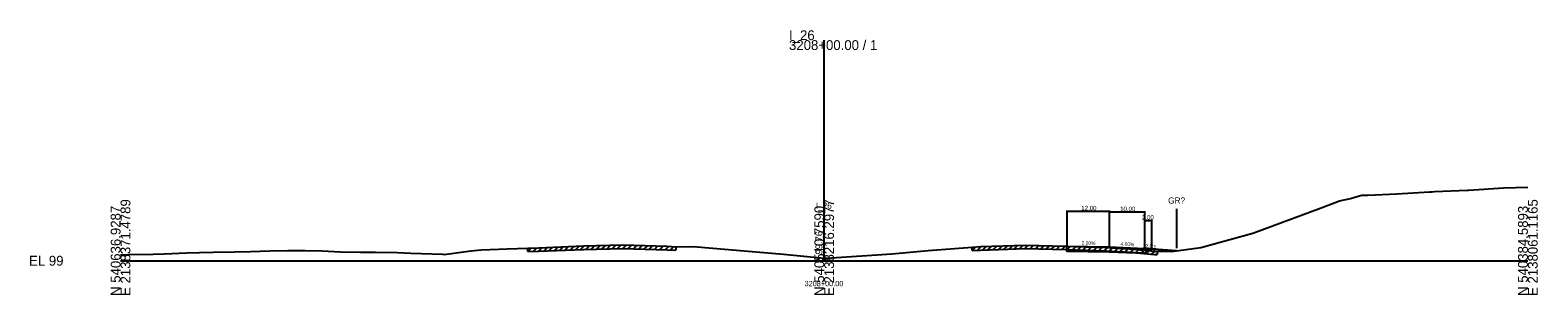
# Model space of a CAD drawing. Extents: x -13101 to 4803, y -924 to 22390.
# Drawn here: x 1974.3 to 2402.8, y 3990.3 to 4065.5 of the extents above; entities that cross this region are included whole.
import ezdxf

# ---------------------------------------------------------------- set-up
doc = ezdxf.new("R2010")
doc.units = 0
for name, color, linetype in [('RD_GPK_XS_Cell', 7, 'Continuous'), ('RD_XD_TX_Width', 7, 'Continuous'), ('RD_XS_Base', 7, 'Continuous'), ('RD_XS_EarthShd', 7, 'Continuous'), ('RD_XS_EwShp', 7, 'Continuous'), ('RD_XS_ExGround', 7, 'Continuous'), ('RD_XS_ExPaveRet', 7, 'Continuous'), ('RD_XS_OSBase', 7, 'Continuous'), ('RD_XS_Pave', 7, 'Continuous'), ('RD_XS_TX_Baseline', 7, 'Continuous'), ('RD_XS_TX_Elev_EX', 7, 'Continuous'), ('RD_XS_TX_ShdSlope', 7, 'Continuous'), ('RD_XS_TX_Slope', 7, 'Continuous'), ('RD_XS_TX_Station', 7, 'Continuous')]:
    doc.layers.add(name, color=color, linetype=linetype)

msp = doc.modelspace()

# ---------------------------------------------------------------- linework, layer by layer
at = {"layer": 'RD_GPK_XS_Cell'}
for p, q in [((2200, 4000), (2200, 4062.69)), ((2000, 4000), (2200, 4000)), ((2200, 4000), (2400, 4000))]:
    msp.add_line(p, q, dxfattribs=at)
at = {"layer": 'RD_XD_TX_Width'}
for p, q in [((2269, 4014.3), (2269, 4004.35)), ((2269, 4014.1), (2281, 4014.1)), ((2281, 4014.3), (2281, 4004.11)), ((2281, 4014.06), (2281, 4004.11)), ((2281, 4013.86), (2291, 4013.86)), ((2291, 4014.06), (2291, 4003.71)), ((2291, 4011.66), (2291, 4003.71)), ((2291, 4011.46), (2293, 4011.46)), ((2293, 4011.66), (2293, 4003.55)), ((2300.1, 4014.73), (2300.1, 4003.55))]:
    msp.add_line(p, q, dxfattribs=at)
at = {"layer": 'RD_XS_Base'}
for p, q in [((2269, 4002.75), (2281, 4002.51)), ((2281, 4002.51), (2291, 4002.11))]:
    msp.add_line(p, q, dxfattribs=at)
at = {"layer": 'RD_XS_EarthShd'}
msp.add_line((2291, 4003.51), (2300.12, 4002.78), dxfattribs=at)
at = {"layer": 'RD_XS_EwShp'}
for points in [[(2269, 4003.75), (2269, 4004.15), (2280.2, 4003.79), (2286.74, 4003.42), (2291.5, 4002.98), (2291.5, 4002.09), (2291, 4002.11), (2281, 4002.51), (2269, 4002.75)], [(2291.5, 4002.98), (2293.87, 4002.76), (2298.73, 4002.59), (2300.12, 4002.78), (2291, 4003.51), (2291, 4003.11), (2291.5, 4003.09)]]:
    msp.add_lwpolyline(points, close=True, dxfattribs=at)
at = {"layer": 'RD_XS_ExGround'}
msp.add_lwpolyline([(2000, 4001.7), (2002.43, 4001.74), (2009.23, 4001.83), (2012.44, 4001.97), (2018.88, 4002.22), (2022.45, 4002.34), (2026.34, 4002.41), (2032.46, 4002.49), (2036.89, 4002.6), (2042.47, 4002.82), (2047.52, 4002.89), (2052.48, 4002.92), (2057.22, 4002.8), (2062.49, 4002.53), (2068.22, 4002.46), (2072.5, 4002.48), (2078.74, 4002.3), (2082.51, 4002.13), (2085.58, 4002.03), (2091.54, 4001.9), (2091.97, 4001.76), (2098.1, 4002.59), (2099.67, 4002.81), (2102.53, 4003.09), (2109.92, 4003.36), (2115.77, 4003.58), (2118.78, 4003.68), (2131.62, 4004.2), (2142.76, 4004.5), (2155.34, 4004.11), (2157.86, 4003.97), (2162.71, 4004.04), (2188.47, 4001.9), (2200, 4000.76), (2200.63, 4000.7), (2219.21, 4001.97), (2229.56, 4002.9), (2242.03, 4003.89), (2244.39, 4004.02), (2257.18, 4004.46), (2268.69, 4004.16), (2280.2, 4003.79), (2286.74, 4003.42), (2293.87, 4002.76), (2298.73, 4002.59), (2307.08, 4003.73), (2321.87, 4007.8), (2341.23, 4015), (2346.43, 4017.03), (2349.55, 4017.71), (2350.84, 4018.07), (2351.77, 4018.34), (2352.77, 4018.6), (2354.53, 4018.66), (2362.78, 4019.01), (2372.03, 4019.56), (2372.79, 4019.61), (2373.46, 4019.66), (2382.8, 4020.08), (2383.26, 4020.1), (2393.05, 4020.74), (2400, 4020.9)], dxfattribs=at)
at = {"layer": 'RD_XS_ExPaveRet'}
for p, q in [((2115.77, 4002.58), (2116.8, 4003.62)), ((2115.77, 4002.58), (2115.77, 4003.58)), ((2115.77, 4002.58), (2118.78, 4002.68)), ((2117.27, 4002.63), (2118.3, 4003.66)), ((2118.77, 4002.68), (2119.81, 4003.72)), ((2118.78, 4002.68), (2131.62, 4003.2)), ((2120.27, 4002.74), (2121.31, 4003.78)), ((2121.77, 4002.8), (2122.81, 4003.84)), ((2123.27, 4002.86), (2124.31, 4003.9)), ((2124.77, 4002.92), (2125.81, 4003.97)), ((2126.27, 4002.98), (2127.31, 4004.03)), ((2127.77, 4003.04), (2128.81, 4004.09)), ((2129.27, 4003.11), (2130.31, 4004.15)), ((2130.77, 4003.17), (2131.81, 4004.21)), ((2131.62, 4003.2), (2142.76, 4003.5)), ((2132.27, 4003.22), (2133.3, 4004.25)), ((2133.77, 4003.26), (2134.8, 4004.29)), ((2135.27, 4003.3), (2136.3, 4004.33)), ((2136.77, 4003.34), (2137.8, 4004.37)), ((2138.27, 4003.38), (2139.3, 4004.41)), ((2139.77, 4003.42), (2140.8, 4004.45)), ((2141.27, 4003.46), (2142.3, 4004.49)), ((2142.76, 4003.5), (2155.34, 4003.11)), ((2142.77, 4003.5), (2143.74, 4004.47)), ((2144.27, 4003.45), (2145.24, 4004.42)), ((2145.77, 4003.41), (2146.74, 4004.37)), ((2147.27, 4003.36), (2148.24, 4004.33)), ((2148.77, 4003.31), (2149.74, 4004.28)), ((2150.27, 4003.26), (2151.24, 4004.23)), ((2151.77, 4003.22), (2152.74, 4004.19)), ((2153.27, 4003.17), (2154.24, 4004.14)), ((2154.77, 4003.12), (2155.73, 4004.09)), ((2155.34, 4003.11), (2157.86, 4002.97)), ((2156.27, 4003.06), (2157.22, 4004.01)), ((2157.86, 4003.97), (2157.86, 4002.97)), ((2242.03, 4002.89), (2243.09, 4003.95)), ((2242.03, 4002.89), (2242.03, 4003.89)), ((2242.03, 4002.89), (2244.39, 4003.02)), ((2243.53, 4002.97), (2244.59, 4004.03)), ((2244.39, 4003.02), (2257.18, 4003.46)), ((2245.03, 4003.04), (2246.07, 4004.08)), ((2246.53, 4003.09), (2247.57, 4004.13)), ((2248.03, 4003.15), (2249.07, 4004.18)), ((2249.53, 4003.2), (2250.57, 4004.23)), ((2251.03, 4003.25), (2252.07, 4004.28)), ((2252.53, 4003.3), (2253.57, 4004.33)), ((2254.03, 4003.35), (2255.07, 4004.39)), ((2255.53, 4003.4), (2256.57, 4004.44)), ((2257.03, 4003.45), (2258.02, 4004.44)), ((2257.18, 4003.46), (2268.69, 4003.16)), ((2258.53, 4003.42), (2259.51, 4004.4)), ((2260.03, 4003.38), (2261.01, 4004.36)), ((2261.53, 4003.35), (2262.51, 4004.32)), ((2263.03, 4003.31), (2264.01, 4004.28)), ((2264.53, 4003.27), (2265.51, 4004.24)), ((2266.03, 4003.23), (2267.01, 4004.2)), ((2267.53, 4003.19), (2268.51, 4004.17)), ((2268.69, 4003.16), (2280.2, 4002.79)), ((2269.03, 4003.15), (2270, 4004.12)), ((2270.53, 4003.1), (2271.5, 4004.07)), ((2272.03, 4003.05), (2273, 4004.02)), ((2273.53, 4003.01), (2274.5, 4003.98)), ((2275.03, 4002.96), (2276, 4003.93)), ((2276.53, 4002.91), (2277.5, 4003.88)), ((2278.03, 4002.86), (2279, 4003.83)), ((2279.53, 4002.82), (2280.49, 4003.78)), ((2280.2, 4002.79), (2286.74, 4002.42)), ((2281.03, 4002.75), (2281.98, 4003.69)), ((2282.53, 4002.66), (2283.48, 4003.61)), ((2284.03, 4002.58), (2284.98, 4003.52)), ((2285.53, 4002.49), (2286.48, 4003.44)), ((2287.03, 4002.39), (2287.95, 4003.31)), ((2288.53, 4002.26), (2289.45, 4003.17)), ((2290.03, 4002.12), (2290.95, 4003.03)), ((2291.53, 4001.98), (2292.45, 4002.89)), ((2293.03, 4001.84), (2293.95, 4002.76)), ((2294.64, 4002.74), (2294.64, 4001.74)), ((2286.74, 4002.42), (2293.87, 4001.76)), ((2293.87, 4001.76), (2294.64, 4001.74))]:
    msp.add_line(p, q, dxfattribs=at)
at = {"layer": 'RD_XS_OSBase'}
for p, q in [((2269, 4003.75), (2269, 4004.15)), ((2269, 4002.75), (2269, 4003.75)), ((2291, 4003.11), (2291, 4003.51)), ((2291.5, 4003.09), (2291, 4003.11)), ((2291.5, 4002.09), (2291.5, 4003.09)), ((2291, 4002.11), (2291.5, 4002.09))]:
    msp.add_line(p, q, dxfattribs=at)
at = {"layer": 'RD_XS_Pave'}
for p, q in [((2269, 4004.15), (2281, 4003.91)), ((2281, 4003.91), (2291, 4003.51))]:
    msp.add_line(p, q, dxfattribs=at)

# ---------------------------------------------------------------- texts
at = {"layer": 'RD_GPK_XS_Cell'}
for s, p in [('3208+00.00 / 1', (2190, 4059.89)), ('I_26', (2190, 4062.69)), ('EL 99', (1974, 3998.6))]:
    msp.add_text(s, height=2.8, dxfattribs=at).set_placement(p)
for s, p in [('N 540636.9287', (2000, 3990)), ('E 2138371.4789', (2002.8, 3990)), ('N 540510.7590', (2200, 3990)), ('E 2138216.2977', (2202.8, 3990)), ('N 540384.5893', (2400, 3990)), ('E 2138061.1165', (2402.8, 3990))]:
    msp.add_text(s, height=2.8, rotation=90, dxfattribs=at).set_placement(p)
at = {"layer": 'RD_XD_TX_Width'}
for s, p in [('12.00', (2273.07, 4014.35)), ('10.00', (2284.11, 4014.11)), ('2.00', (2290.31, 4011.71))]:
    msp.add_text(s, height=1.25, dxfattribs=at).set_placement(p)
at = {"layer": 'RD_XS_TX_Baseline'}
for s, p in [('I_26', (2197.6, 4014.76)), ('GR?', (2297.77, 4016.24))]:
    msp.add_text(s, height=1.75, dxfattribs=at).set_placement(p)
at = {"layer": 'RD_XS_TX_Elev_EX'}
msp.add_text('99.76', height=2, rotation=90, dxfattribs=at).set_placement((2199.5, 4001.76))
at = {"layer": 'RD_XS_TX_ShdSlope'}
msp.add_text('12.5:1', height=1, rotation=355.4261, dxfattribs=at).set_placement((2290.51, 4003.8))
msp.add_text('12.5:1', height=1, rotation=355.4261, dxfattribs=at).set_placement((2290.51, 4003.8))
at = {"layer": 'RD_XS_TX_Slope'}
for s, rotation, p in [('2.00%', 358.8542, (2273.16, 4004.57)), ('4.00%', 357.7094, (2284.22, 4004.28))]:
    msp.add_text(s, height=1, rotation=rotation, dxfattribs=at).set_placement(p)
at = {"layer": 'RD_XS_TX_Station'}
msp.add_text('3208+00.00', height=1.5, dxfattribs=at).set_placement((2194.43, 3992.76))

doc.saveas('drawing.dxf')
